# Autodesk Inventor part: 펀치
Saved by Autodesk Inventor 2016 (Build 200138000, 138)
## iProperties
Created: 2024-08
Part Number: 펀치
Material: 일반
Document SubType Name: Modeling
Designer: pc-2
Density: 1 g/cm^3
Appearance: 기본값
Author: jhkim
Sending System: Autodesk Inventor 2025
Preprocessor: ST-DEVELOPER v20
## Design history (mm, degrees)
node "펀치1"
node "솔리드2"
node "솔리드1"
